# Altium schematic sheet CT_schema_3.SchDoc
size 511 x 403 mm
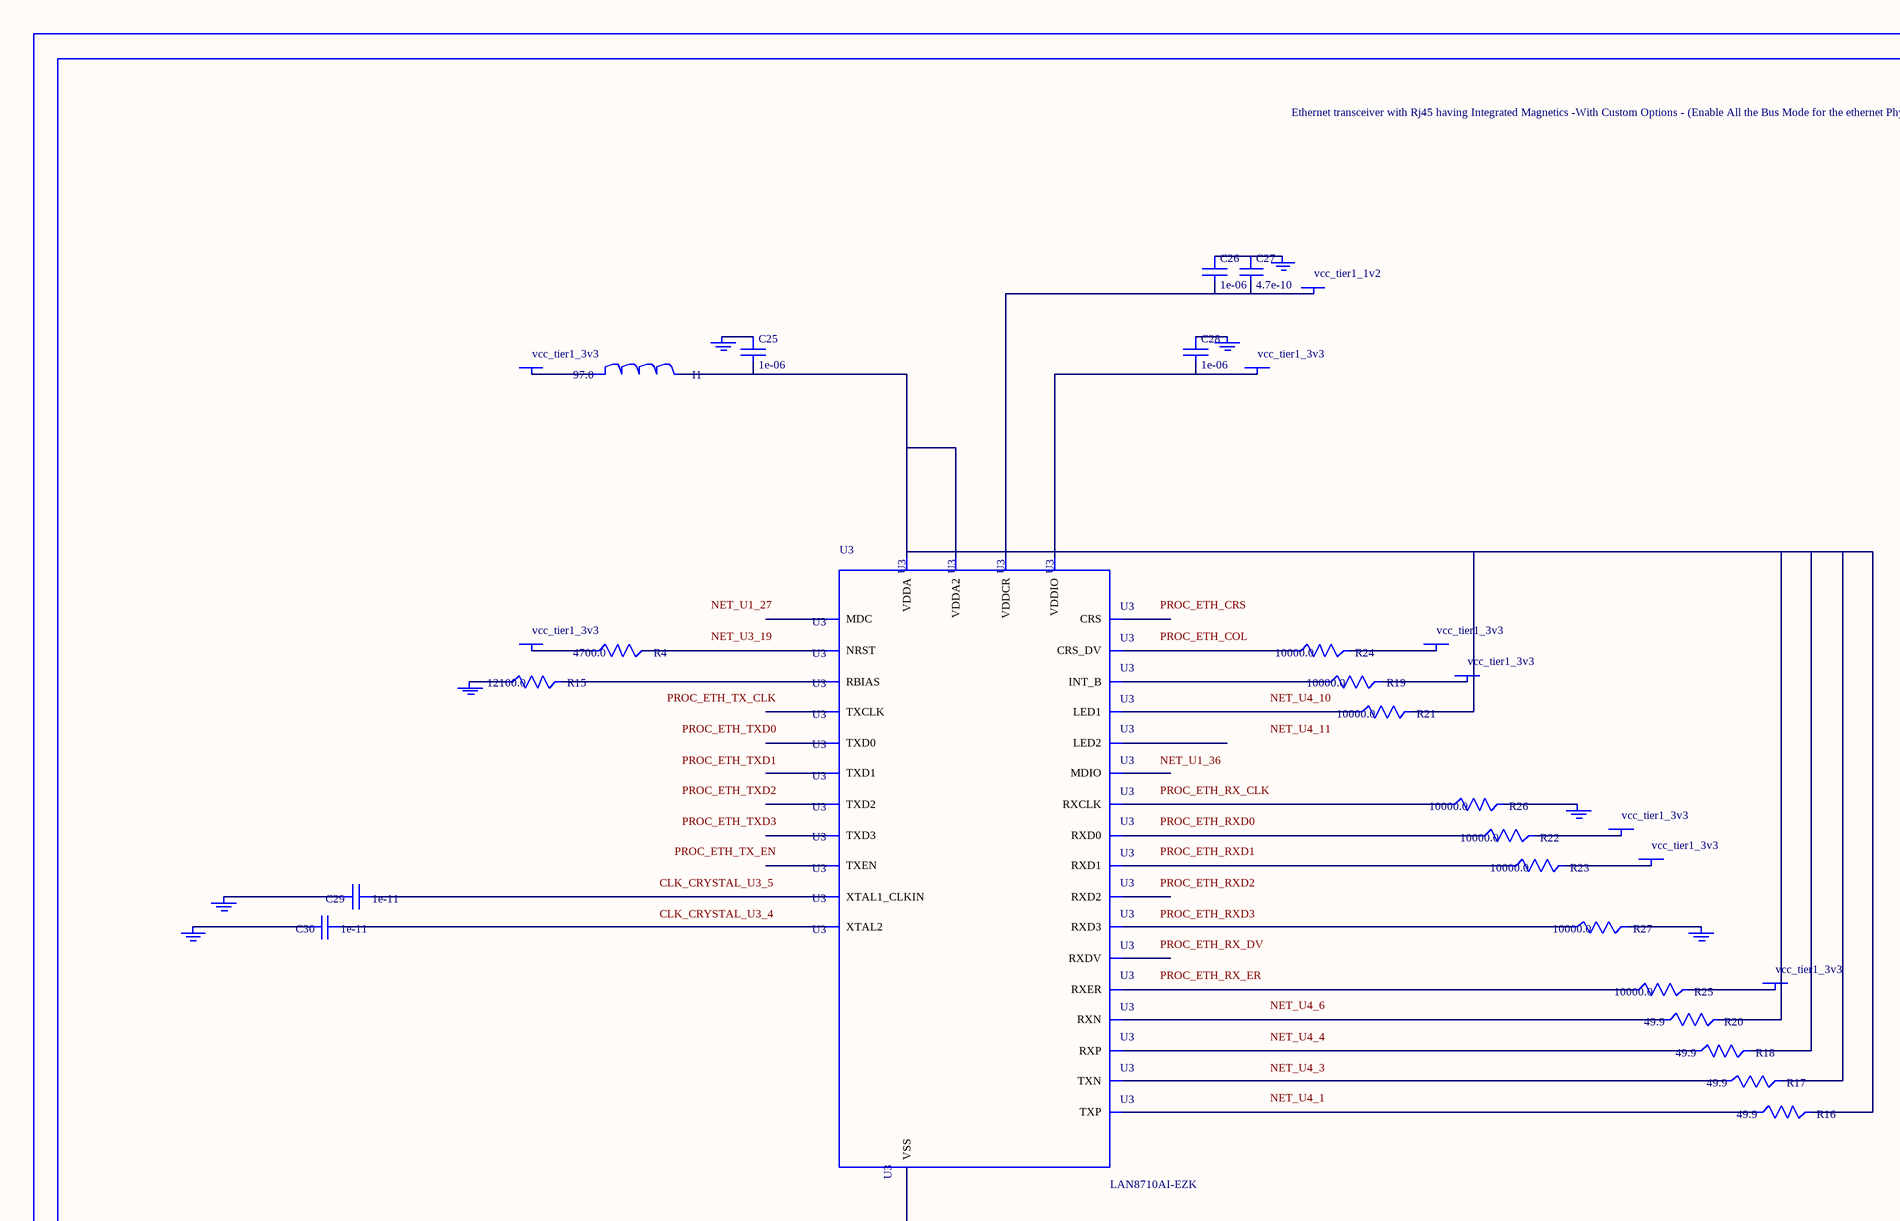
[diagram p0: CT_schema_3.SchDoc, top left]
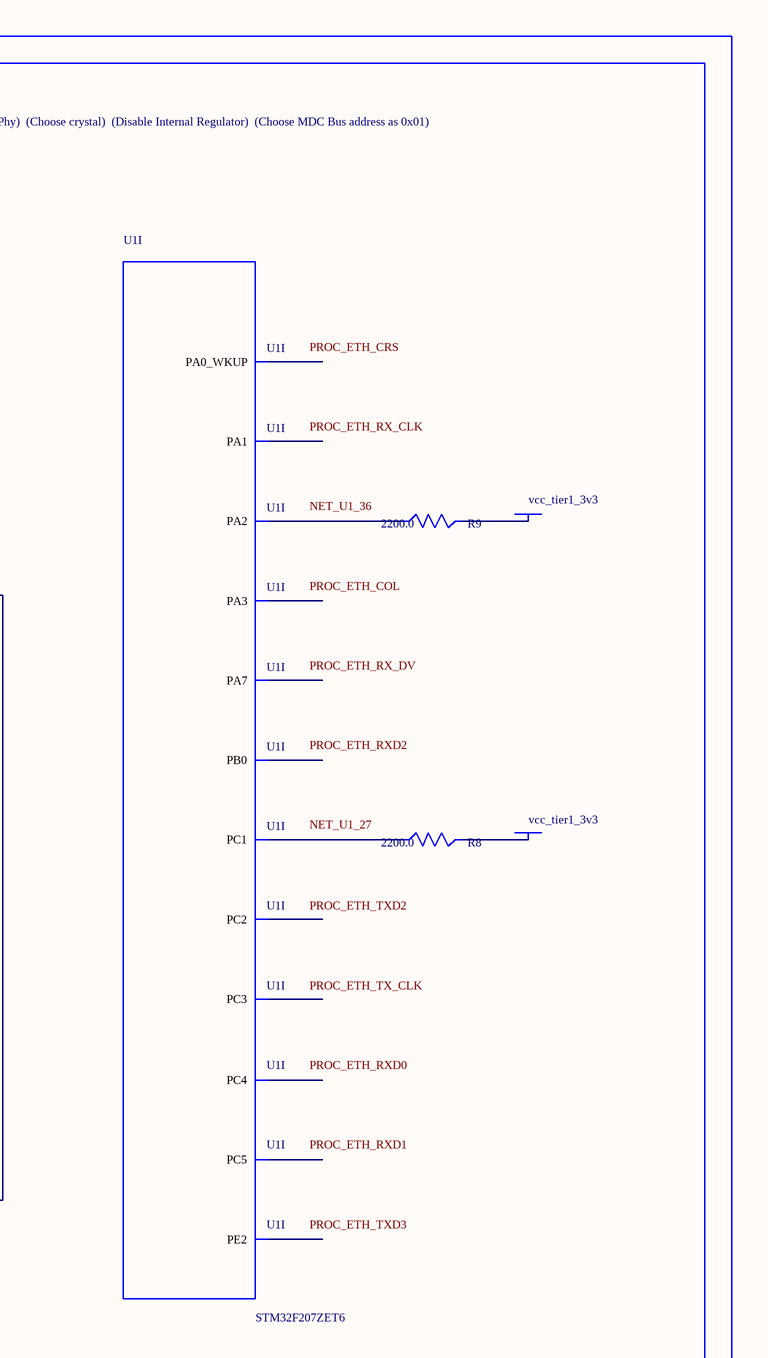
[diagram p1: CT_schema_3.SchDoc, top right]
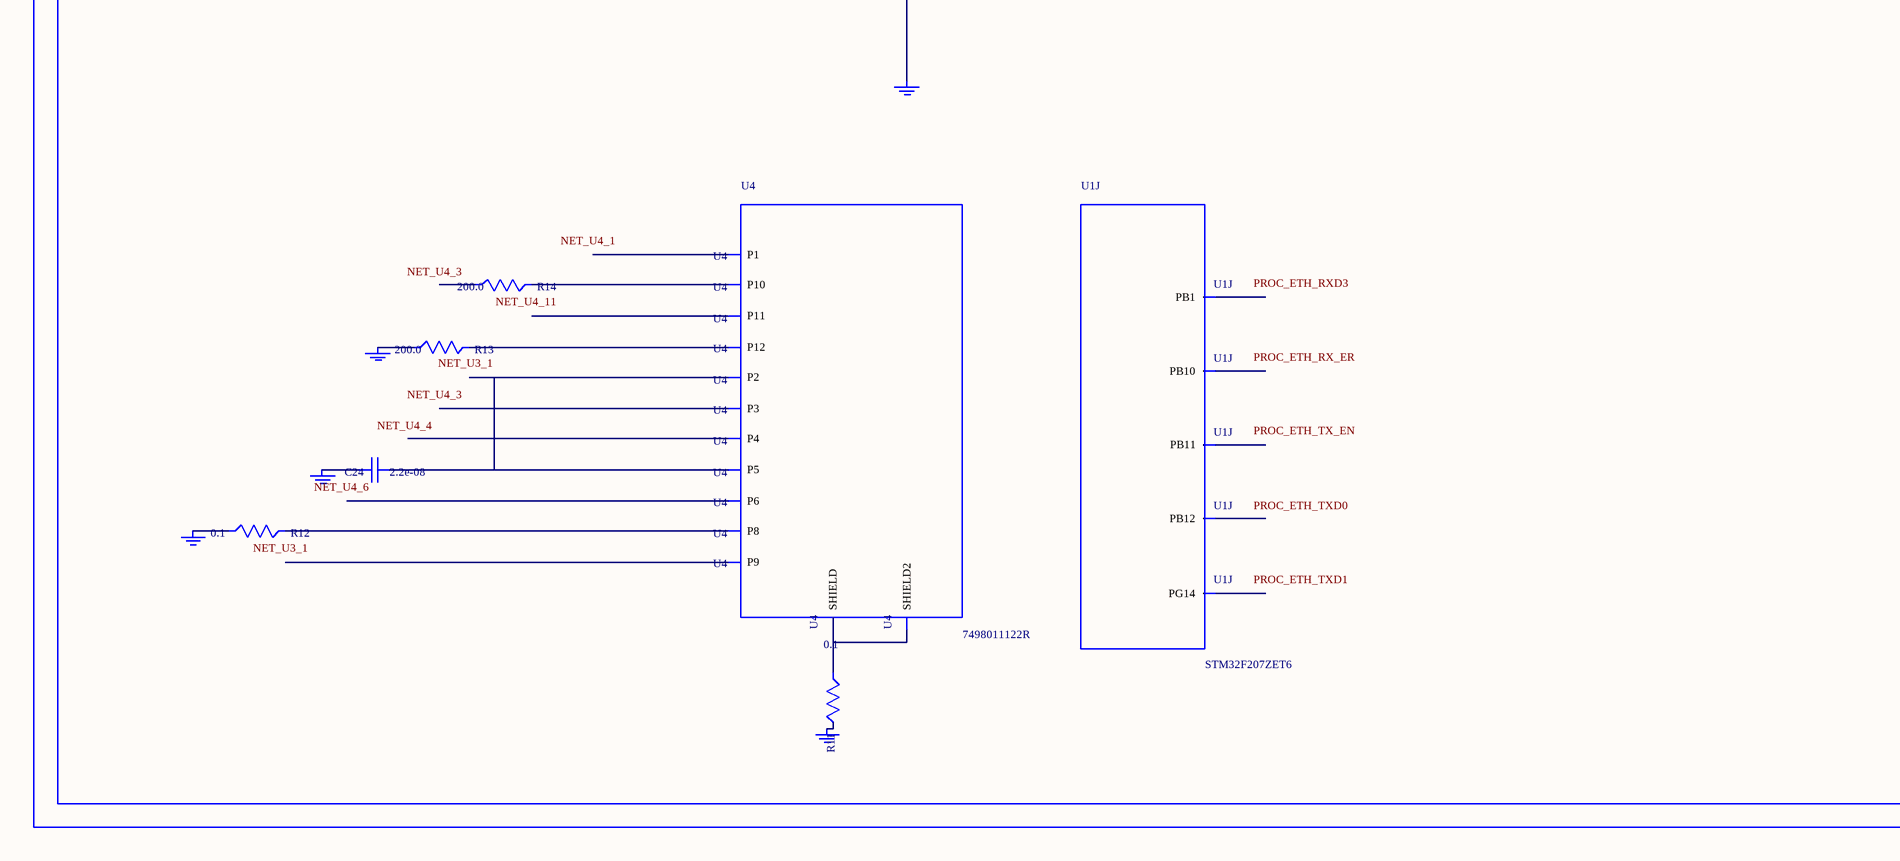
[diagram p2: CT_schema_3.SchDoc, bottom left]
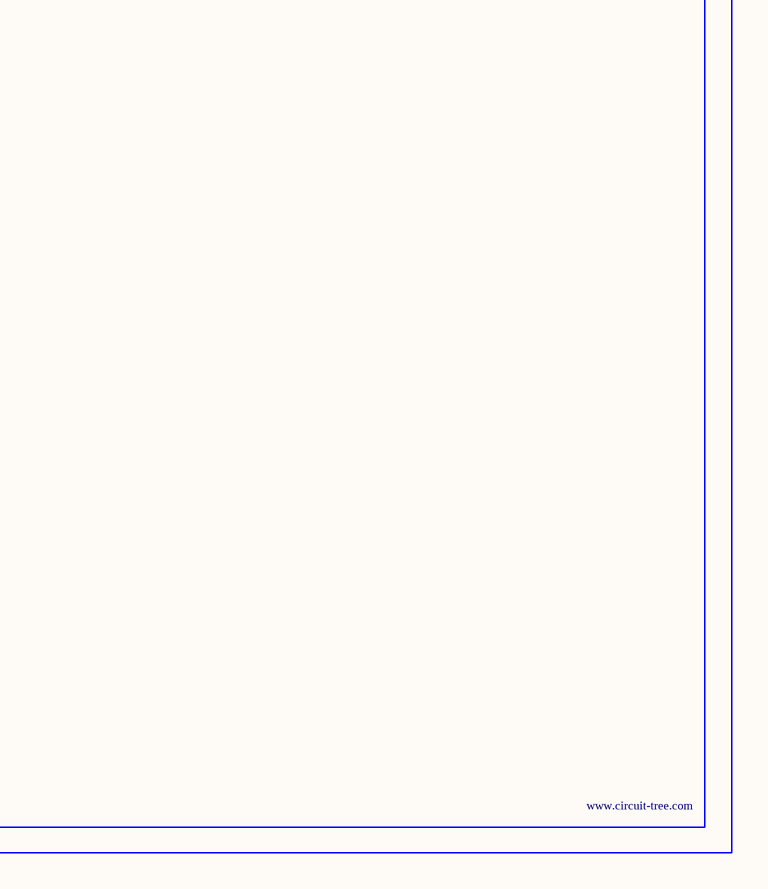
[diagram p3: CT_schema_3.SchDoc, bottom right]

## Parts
BORDER2  (no value)
C24  2.2e-08  [C0402]
C25  1e-06  [C0603]
C26  1e-06  [C0603]
C27  4.7e-10  [C0603]
C28  1e-06  [C0603]
C29  1e-11  [C0402]
C30  1e-11  [C0402]
GND_INSTANCE_2_0  (no value)
GND_INSTANCE_2_1  (no value)
GND_INSTANCE_2_2  (no value)
GND_INSTANCE_2_3  (no value)
GND_INSTANCE_2_4  (no value)
GND_INSTANCE_2_5  (no value)
GND_INSTANCE_2_6  (no value)
GND_INSTANCE_2_7  (no value)
GND_INSTANCE_2_8  (no value)
GND_INSTANCE_2_9  (no value)
GND_INSTANCE_2_10  (no value)
GND_INSTANCE_2_11  (no value)
GND_INSTANCE_2_12  (no value)
I1  97.0  [R0603]
POWER_INSTANCE_2_0  vcc_tier1_3v3
POWER_INSTANCE_2_1  vcc_tier1_1v2
POWER_INSTANCE_2_2  vcc_tier1_3v3
POWER_INSTANCE_2_3  vcc_tier1_3v3
POWER_INSTANCE_2_4  vcc_tier1_3v3
POWER_INSTANCE_2_5  vcc_tier1_3v3
POWER_INSTANCE_2_6  vcc_tier1_3v3
POWER_INSTANCE_2_7  vcc_tier1_3v3
POWER_INSTANCE_2_8  vcc_tier1_3v3
POWER_INSTANCE_2_9  vcc_tier1_3v3
POWER_INSTANCE_2_10  vcc_tier1_3v3
R4  4700.0  [R0603]
R8  2200.0  [R0603]
R9  2200.0  [R0603]
R11  0.1  [R0603]
R12  0.1  [R0603]
R13  200.0  [R0603]
R14  200.0  [R0603]
R15  12100.0  [R0603]
R16  49.9  [R0603]
R17  49.9  [R0603]
R18  49.9  [R0603]
R19  10000.0  [R0603]
R20  49.9  [R0603]
R21  10000.0  [R0603]
R22  10000.0  [R0603]
R23  10000.0  [R0603]
R24  10000.0  [R0603]
R25  10000.0  [R0603]
R26  10000.0  [R0603]
R27  10000.0  [R0603]
U1  STM32F207ZET6  [LQFP144]  (parts I,J of 13)
U3  LAN8710AI-EZK  [QFN-32]
U4  7498011122R  [7498011122R]

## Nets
NetC24_1: C24.1 U4.2(P2) U4.5(P5)
NetC24_2: C24.2 GND_INSTANCE_2_9.0(GND)
NetC25_1: C25.1 GND_INSTANCE_2_0.0(GND)
NetC25_2: C25.2 I1.2 R16.2 R17.2 R18.2 R20.2 R21.2 U3.1(VDDA) U3.27(VDDA2)
NetC26_1: C26.1 C27.1 GND_INSTANCE_2_3.0(GND)
NetC26_2: C26.2 C27.2 POWER_INSTANCE_2_1.0(PWR) U3.6(VDDCR)
NetC28_1: C28.1 GND_INSTANCE_2_6.0(GND)
NetC28_2: C28.2 POWER_INSTANCE_2_4.0(PWR) U3.12(VDDIO)
NetC29_1: C29.1 U3.5(XTAL1_CLKIN)
NetC29_2: C29.2 GND_INSTANCE_2_2.0(GND)
NetC30_1: C30.1 U3.4(XTAL2)
NetC30_2: C30.2 GND_INSTANCE_2_1.0(GND)
NetGND_INSTANCE_2_4_0: GND_INSTANCE_2_4.0(GND) R26.2
NetGND_INSTANCE_2_5_0: GND_INSTANCE_2_5.0(GND) R27.2
NetGND_INSTANCE_2_7_0: GND_INSTANCE_2_7.0(GND) R15.1
NetGND_INSTANCE_2_8_0: GND_INSTANCE_2_8.0(GND) U3.EXP(VSS)
NetGND_INSTANCE_2_10_0: GND_INSTANCE_2_10.0(GND) R12.1
NetGND_INSTANCE_2_11_0: GND_INSTANCE_2_11.0(GND) R13.1
NetGND_INSTANCE_2_12_0: GND_INSTANCE_2_12.0(GND) R11.2
NetI1_1: I1.1 POWER_INSTANCE_2_0.0(PWR)
NetPOWER_INSTANCE_2_2_0: POWER_INSTANCE_2_2.0(PWR) R23.2
NetPOWER_INSTANCE_2_3_0: POWER_INSTANCE_2_3.0(PWR) R22.2
NetPOWER_INSTANCE_2_5_0: POWER_INSTANCE_2_5.0(PWR) R25.2
NetPOWER_INSTANCE_2_6_0: POWER_INSTANCE_2_6.0(PWR) R24.2
NetPOWER_INSTANCE_2_7_0: POWER_INSTANCE_2_7.0(PWR) R19.2
NetPOWER_INSTANCE_2_8_0: POWER_INSTANCE_2_8.0(PWR) R4.1
NetPOWER_INSTANCE_2_9_0: POWER_INSTANCE_2_9.0(PWR) R8.2
NetPOWER_INSTANCE_2_10_0: POWER_INSTANCE_2_10.0(PWR) R9.2
NetR4_2: R4.2 U3.19(NRST)
NetR8_1: R8.1 U1.27(PC1)
NetR9_1: R9.1 U1.36(PA2)
NetR11_1: R11.1 U4.13(SHIELD) U4.14(SHIELD2)
NetR12_2: R12.2 U4.8(P8)
NetR13_2: R13.2 U4.12(P12)
NetR14_2: R14.2 U4.10(P10)
NetR15_2: R15.2 U3.32(RBIAS)
NetR16_1: R16.1 U3.29(TXP)
NetR17_1: R17.1 U3.28(TXN)
NetR18_1: R18.1 U3.31(RXP)
NetR19_1: R19.1 U3.18(INT_B)
NetR20_1: R20.1 U3.30(RXN)
NetR21_1: R21.1 U3.3(LED1)
NetR22_1: R22.1 U3.11(RXD0)
NetR23_1: R23.1 U3.10(RXD1)
NetR24_1: R24.1 U3.15(CRS_DV)
NetR25_1: R25.1 U3.13(RXER)
NetR26_1: R26.1 U3.7(RXCLK)
NetR27_1: R27.1 U3.8(RXD3)

Not connected (* = marked no-connect by the designer): R14 1; U1 1(PE2) 28(PC2) 29(PC3) 34(PA0_WKUP) 35(PA1) 37(PA3) 43(PA7) 44(PC4) 45(PC5) 46(PB0) 47(PB1) 69(PB10) 70(PB11) 73(PB12) 129(PG14); U3 2(LED2) 9(RXD2) 14(CRS) 16(MDIO) 17(MDC) 20(TXCLK) 21(TXEN) 22(TXD0) 23(TXD1) 24(TXD2) 25(TXD3) 26(RXDV); U4 1(P1) 3(P3) 4(P4) 6(P6) 9(P9) 11(P11)

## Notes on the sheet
- Labels drawn without touching a wire or pin: CLK_CRYSTAL_U3_4, CLK_CRYSTAL_U3_5, NET_U1_27, NET_U1_36, NET_U3_1, NET_U3_19, NET_U4_1, NET_U4_3, NET_U4_4, NET_U4_6, NET_U4_10, NET_U4_11, PROC_ETH_COL, PROC_ETH_CRS, PROC_ETH_RX_CLK, PROC_ETH_RX_DV, PROC_ETH_RX_ER, PROC_ETH_RXD0, PROC_ETH_RXD1, PROC_ETH_RXD2, PROC_ETH_RXD3, PROC_ETH_TX_CLK, PROC_ETH_TX_EN, PROC_ETH_TXD0, PROC_ETH_TXD1, PROC_ETH_TXD2, PROC_ETH_TXD3

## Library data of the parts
BORDER2 = BORDER_PAGE2
C24 = C0402C223K3RAC
C25 C26 C28 = C0603C105K3RACTU
C27 = 06031C471KAZ2A
C29 C30 = C0402C100K3GACTU
GND_INSTANCE_2_0-GND_INSTANCE_2_12 = GND
I1 = I1
POWER_INSTANCE_2_0-POWER_INSTANCE_2_10 = PWR
R4 = RC0603JR-074K7L
R8 R9 = RC0603JR-072K2L
R11 R12 = ERJ-3RSFR10V
R13 R14 = RC0603JR-07200RL
R15 = TNPW060312K1BEEA
R16-R18 R20 = RC0603FR-0749R9L
R19 R21-R27 = RC0603JR-0710KL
